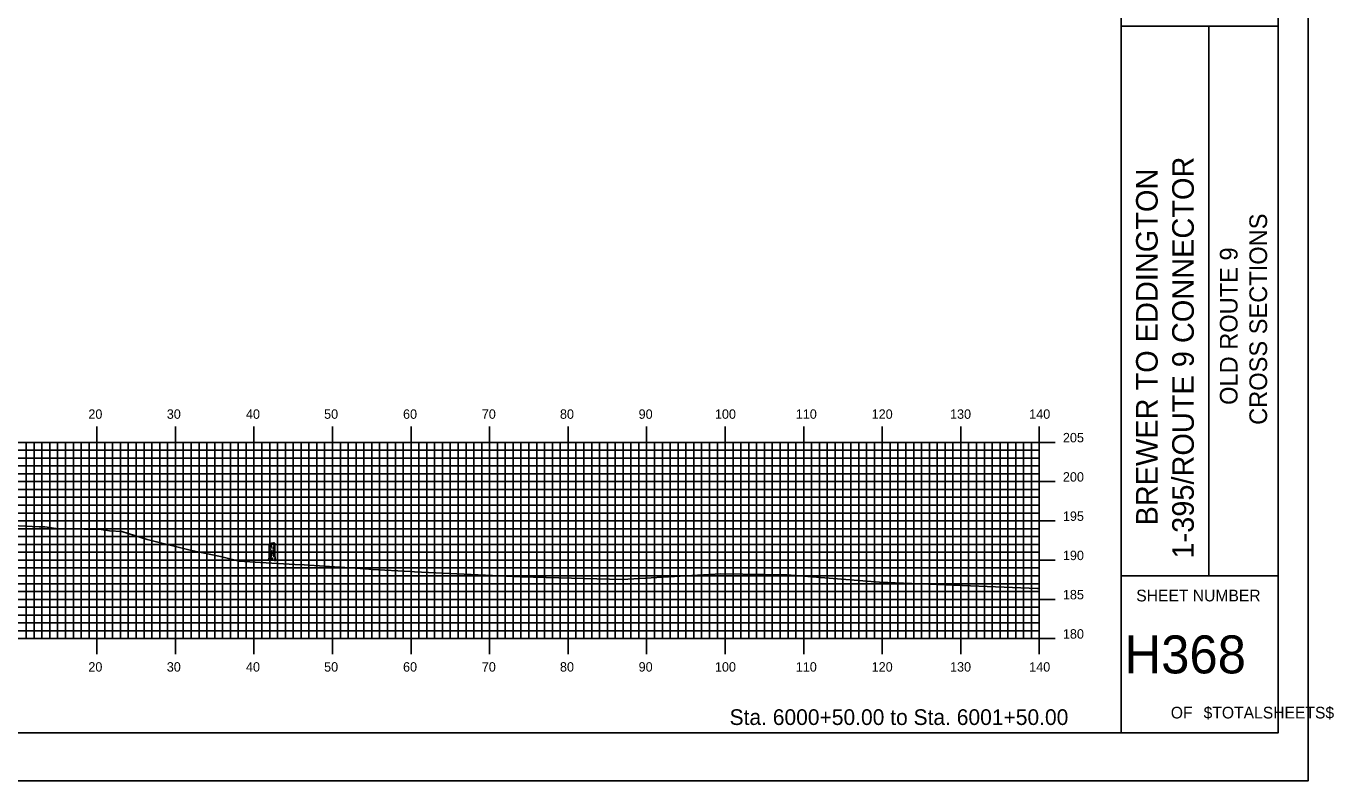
# Model space of a CAD drawing. Extents: x 851300 to 851643, y 366898 to 367118.
# Drawn here: x 851476.5 to 851643, y 366898.4 to 366994.5 of the extents above; entities that cross this region are included whole.
import ezdxf

# ---------------------------------------------------------------- set-up
doc = ezdxf.new("R2010")
doc.units = 0
for name, color, linetype in [('BORDER', 7, 'Continuous'), ('H_V ANNOTATION', 7, 'Continuous'), ('MAJOR', 7, 'Continuous'), ('MINOR', 7, 'Continuous'), ('PLOT BOUNDARY', 7, 'Continuous'), ('S_Roadway_Centerline', 7, 'Continuous'), ('S_Trees_Conifer_NonPay', 7, 'Continuous')]:
    doc.layers.add(name, color=color, linetype=linetype)

msp = doc.modelspace()

# ---------------------------------------------------------------- linework, layer by layer
at = {"layer": 'BORDER'}
for p, q in [((851615.9, 366904.47), (851615.9, 367114.47)), ((851615.9, 366994.48), (851635.9, 366994.48)), ((851627.09, 366924.48), (851627.09, 366994.48)), ((851615.9, 366924.48), (851635.9, 366924.48))]:
    msp.add_line(p, q, dxfattribs=at)
msp.add_lwpolyline([(851315.9, 366904.47), (851635.9, 366904.47), (851635.9, 367114.47), (851315.9, 367114.47)], close=True, dxfattribs=at)
at = {"layer": 'MAJOR'}
for p, q in [((851485.5, 366943.48), (851485.5, 366941.47)), ((851495.5, 366943.48), (851495.5, 366941.47)), ((851505.5, 366943.48), (851505.5, 366941.47)), ((851515.5, 366943.48), (851515.5, 366941.47)), ((851525.5, 366943.48), (851525.5, 366941.47)), ((851535.5, 366943.48), (851535.5, 366941.47)), ((851545.5, 366943.48), (851545.5, 366941.47)), ((851555.5, 366943.48), (851555.5, 366941.47)), ((851565.5, 366943.48), (851565.5, 366941.47)), ((851575.5, 366943.48), (851575.5, 366941.47)), ((851585.5, 366943.48), (851585.5, 366941.47)), ((851595.5, 366943.48), (851595.5, 366941.47)), ((851605.5, 366943.48), (851605.5, 366941.47)), ((851325.5, 366941.47), (851605.5, 366941.47)), ((851325.5, 366941.47), (851605.5, 366941.47)), ((851485.5, 366916.47), (851485.5, 366941.47)), ((851495.5, 366916.47), (851495.5, 366941.47)), ((851505.5, 366916.47), (851505.5, 366941.47)), ((851515.5, 366916.47), (851515.5, 366941.47)), ((851525.5, 366916.47), (851525.5, 366941.47)), ((851535.5, 366916.47), (851535.5, 366941.47)), ((851545.5, 366916.47), (851545.5, 366941.47)), ((851555.5, 366916.47), (851555.5, 366941.47)), ((851565.5, 366916.47), (851565.5, 366941.47)), ((851575.5, 366916.47), (851575.5, 366941.47)), ((851585.5, 366916.47), (851585.5, 366941.47)), ((851595.5, 366916.47), (851595.5, 366941.47)), ((851607.51, 366941.47), (851603.5, 366941.47)), ((851605.5, 366916.47), (851605.5, 366941.47)), ((851605.5, 366916.47), (851605.5, 366941.47)), ((851325.5, 366936.47), (851605.5, 366936.47)), ((851607.51, 366936.47), (851603.5, 366936.47)), ((851325.5, 366931.47), (851605.5, 366931.47)), ((851607.51, 366931.47), (851603.5, 366931.47)), ((851325.5, 366926.47), (851605.5, 366926.47)), ((851607.51, 366926.47), (851603.5, 366926.47)), ((851325.5, 366921.47), (851605.5, 366921.47)), ((851607.51, 366921.47), (851603.5, 366921.47)), ((851325.5, 366916.47), (851605.5, 366916.47)), ((851325.5, 366916.47), (851605.5, 366916.47)), ((851485.5, 366914.47), (851485.5, 366916.47)), ((851495.5, 366914.47), (851495.5, 366916.47)), ((851505.5, 366914.47), (851505.5, 366916.47)), ((851515.5, 366914.47), (851515.5, 366916.47)), ((851525.5, 366914.47), (851525.5, 366916.47)), ((851535.5, 366914.47), (851535.5, 366916.47)), ((851545.5, 366914.47), (851545.5, 366916.47)), ((851555.5, 366914.47), (851555.5, 366916.47)), ((851565.5, 366914.47), (851565.5, 366916.47)), ((851575.5, 366914.47), (851575.5, 366916.47)), ((851585.5, 366914.47), (851585.5, 366916.47)), ((851595.5, 366914.47), (851595.5, 366916.47)), ((851607.51, 366916.47), (851603.5, 366916.47)), ((851605.5, 366914.47), (851605.5, 366916.47))]:
    msp.add_line(p, q, dxfattribs=at)
at = {"layer": 'MINOR'}
for p, q in [((851476.5, 366916.47), (851476.5, 366941.47)), ((851477.5, 366916.47), (851477.5, 366941.47)), ((851478.5, 366916.47), (851478.5, 366941.47)), ((851479.5, 366916.47), (851479.5, 366941.47)), ((851480.5, 366916.47), (851480.5, 366941.47)), ((851481.5, 366916.47), (851481.5, 366941.47)), ((851482.5, 366916.47), (851482.5, 366941.47)), ((851483.5, 366916.47), (851483.5, 366941.47)), ((851484.5, 366916.47), (851484.5, 366941.47)), ((851486.5, 366916.47), (851486.5, 366941.47)), ((851487.5, 366916.47), (851487.5, 366941.47)), ((851488.5, 366916.47), (851488.5, 366941.47)), ((851489.5, 366916.47), (851489.5, 366941.47)), ((851490.5, 366916.47), (851490.5, 366941.47)), ((851491.5, 366916.47), (851491.5, 366941.47)), ((851492.5, 366916.47), (851492.5, 366941.47)), ((851493.5, 366916.47), (851493.5, 366941.47)), ((851494.5, 366916.47), (851494.5, 366941.47)), ((851496.5, 366916.47), (851496.5, 366941.47)), ((851497.5, 366916.47), (851497.5, 366941.47)), ((851498.5, 366916.47), (851498.5, 366941.47)), ((851499.5, 366916.47), (851499.5, 366941.47)), ((851500.5, 366916.47), (851500.5, 366941.47)), ((851501.5, 366916.47), (851501.5, 366941.47)), ((851502.5, 366916.47), (851502.5, 366941.47)), ((851503.5, 366916.47), (851503.5, 366941.47)), ((851504.5, 366916.47), (851504.5, 366941.47)), ((851506.5, 366916.47), (851506.5, 366941.47)), ((851507.5, 366916.47), (851507.5, 366941.47)), ((851508.5, 366916.47), (851508.5, 366941.47)), ((851509.5, 366916.47), (851509.5, 366941.47)), ((851510.5, 366916.47), (851510.5, 366941.47)), ((851511.5, 366916.47), (851511.5, 366941.47)), ((851512.5, 366916.47), (851512.5, 366941.47)), ((851513.5, 366916.47), (851513.5, 366941.47)), ((851514.5, 366916.47), (851514.5, 366941.47)), ((851516.5, 366916.47), (851516.5, 366941.47)), ((851517.5, 366916.47), (851517.5, 366941.47)), ((851518.5, 366916.47), (851518.5, 366941.47)), ((851519.5, 366916.47), (851519.5, 366941.47)), ((851520.5, 366916.47), (851520.5, 366941.47)), ((851521.5, 366916.47), (851521.5, 366941.47)), ((851522.5, 366916.47), (851522.5, 366941.47)), ((851523.5, 366916.47), (851523.5, 366941.47)), ((851524.5, 366916.47), (851524.5, 366941.47)), ((851526.5, 366916.47), (851526.5, 366941.47)), ((851527.5, 366916.47), (851527.5, 366941.47)), ((851528.5, 366916.47), (851528.5, 366941.47)), ((851529.5, 366916.47), (851529.5, 366941.47)), ((851530.5, 366916.47), (851530.5, 366941.47)), ((851531.5, 366916.47), (851531.5, 366941.47)), ((851532.5, 366916.47), (851532.5, 366941.47)), ((851533.5, 366916.47), (851533.5, 366941.47)), ((851534.5, 366916.47), (851534.5, 366941.47)), ((851536.5, 366916.47), (851536.5, 366941.47)), ((851537.5, 366916.47), (851537.5, 366941.47)), ((851538.5, 366916.47), (851538.5, 366941.47)), ((851539.5, 366916.47), (851539.5, 366941.47)), ((851540.5, 366916.47), (851540.5, 366941.47)), ((851541.5, 366916.47), (851541.5, 366941.47)), ((851542.5, 366916.47), (851542.5, 366941.47)), ((851543.5, 366916.47), (851543.5, 366941.47)), ((851544.5, 366916.47), (851544.5, 366941.47)), ((851546.5, 366916.47), (851546.5, 366941.47)), ((851547.5, 366916.47), (851547.5, 366941.47)), ((851548.5, 366916.47), (851548.5, 366941.47)), ((851549.5, 366916.47), (851549.5, 366941.47)), ((851550.5, 366916.47), (851550.5, 366941.47)), ((851551.5, 366916.47), (851551.5, 366941.47)), ((851552.5, 366916.47), (851552.5, 366941.47)), ((851553.5, 366916.47), (851553.5, 366941.47)), ((851554.5, 366916.47), (851554.5, 366941.47)), ((851556.5, 366916.47), (851556.5, 366941.47)), ((851557.5, 366916.47), (851557.5, 366941.47)), ((851558.5, 366916.47), (851558.5, 366941.47)), ((851559.5, 366916.47), (851559.5, 366941.47)), ((851560.5, 366916.47), (851560.5, 366941.47)), ((851561.5, 366916.47), (851561.5, 366941.47)), ((851562.5, 366916.47), (851562.5, 366941.47)), ((851563.5, 366916.47), (851563.5, 366941.47)), ((851564.5, 366916.47), (851564.5, 366941.47)), ((851566.5, 366916.47), (851566.5, 366941.47)), ((851567.5, 366916.47), (851567.5, 366941.47)), ((851568.5, 366916.47), (851568.5, 366941.47)), ((851569.5, 366916.47), (851569.5, 366941.47)), ((851570.5, 366916.47), (851570.5, 366941.47)), ((851571.5, 366916.47), (851571.5, 366941.47)), ((851572.5, 366916.47), (851572.5, 366941.47)), ((851573.5, 366916.47), (851573.5, 366941.47)), ((851574.5, 366916.47), (851574.5, 366941.47)), ((851576.5, 366916.47), (851576.5, 366941.47)), ((851577.5, 366916.47), (851577.5, 366941.47)), ((851578.5, 366916.47), (851578.5, 366941.47)), ((851579.5, 366916.47), (851579.5, 366941.47)), ((851580.5, 366916.47), (851580.5, 366941.47)), ((851581.5, 366916.47), (851581.5, 366941.47)), ((851582.5, 366916.47), (851582.5, 366941.47)), ((851583.5, 366916.47), (851583.5, 366941.47)), ((851584.5, 366916.47), (851584.5, 366941.47)), ((851586.5, 366916.47), (851586.5, 366941.47)), ((851587.5, 366916.47), (851587.5, 366941.47)), ((851588.5, 366916.47), (851588.5, 366941.47)), ((851589.5, 366916.47), (851589.5, 366941.47)), ((851590.5, 366916.47), (851590.5, 366941.47)), ((851591.5, 366916.47), (851591.5, 366941.47)), ((851592.5, 366916.47), (851592.5, 366941.47)), ((851593.5, 366916.47), (851593.5, 366941.47)), ((851594.5, 366916.47), (851594.5, 366941.47)), ((851596.5, 366916.47), (851596.5, 366941.47)), ((851597.5, 366916.47), (851597.5, 366941.47)), ((851598.5, 366916.47), (851598.5, 366941.47)), ((851599.5, 366916.47), (851599.5, 366941.47)), ((851600.5, 366916.47), (851600.5, 366941.47)), ((851601.5, 366916.47), (851601.5, 366941.47)), ((851602.5, 366916.47), (851602.5, 366941.47)), ((851603.5, 366916.47), (851603.5, 366941.47)), ((851604.5, 366916.47), (851604.5, 366941.47)), ((851325.5, 366940.47), (851605.5, 366940.47)), ((851325.5, 366939.47), (851605.5, 366939.47)), ((851605.5, 366940.47), (851603.5, 366940.47)), ((851605.5, 366939.47), (851603.5, 366939.47)), ((851325.5, 366938.47), (851605.5, 366938.47)), ((851325.5, 366937.47), (851605.5, 366937.47)), ((851605.5, 366938.47), (851603.5, 366938.47)), ((851605.5, 366937.47), (851603.5, 366937.47)), ((851325.5, 366935.47), (851605.5, 366935.47)), ((851325.5, 366934.47), (851605.5, 366934.47)), ((851605.5, 366935.47), (851603.5, 366935.47)), ((851605.5, 366934.47), (851603.5, 366934.47)), ((851325.5, 366933.47), (851605.5, 366933.47)), ((851325.5, 366932.47), (851605.5, 366932.47)), ((851605.5, 366933.47), (851603.5, 366933.47)), ((851605.5, 366932.47), (851603.5, 366932.47)), ((851325.5, 366930.47), (851605.5, 366930.47)), ((851325.5, 366929.47), (851605.5, 366929.47)), ((851605.5, 366930.47), (851603.5, 366930.47)), ((851605.5, 366929.47), (851603.5, 366929.47)), ((851325.5, 366928.47), (851605.5, 366928.47)), ((851325.5, 366927.47), (851605.5, 366927.47)), ((851605.5, 366928.47), (851603.5, 366928.47)), ((851605.5, 366927.47), (851603.5, 366927.47)), ((851325.5, 366925.47), (851605.5, 366925.47)), ((851325.5, 366924.47), (851605.5, 366924.47)), ((851605.5, 366925.47), (851603.5, 366925.47)), ((851605.5, 366924.47), (851603.5, 366924.47)), ((851325.5, 366923.47), (851605.5, 366923.47)), ((851325.5, 366922.47), (851605.5, 366922.47)), ((851605.5, 366923.47), (851603.5, 366923.47)), ((851605.5, 366922.47), (851603.5, 366922.47)), ((851325.5, 366920.47), (851605.5, 366920.47)), ((851325.5, 366919.47), (851605.5, 366919.47)), ((851605.5, 366920.47), (851603.5, 366920.47)), ((851605.5, 366919.47), (851603.5, 366919.47)), ((851325.5, 366918.47), (851605.5, 366918.47)), ((851325.5, 366917.47), (851605.5, 366917.47)), ((851605.5, 366918.47), (851603.5, 366918.47)), ((851605.5, 366917.47), (851603.5, 366917.47))]:
    msp.add_line(p, q, dxfattribs=at)
at = {"layer": 'PLOT BOUNDARY'}
msp.add_lwpolyline([(851299.72, 366898.35), (851639.72, 366898.35), (851639.72, 367118.35), (851299.72, 367118.35)], close=True, dxfattribs=at)
at = {"layer": 'S_Roadway_Centerline'}
msp.add_lwpolyline([(851471.09, 366931.06), (851478.15, 366930.7), (851478.87, 366930.71), (851480.28, 366930.51), (851481.66, 366930.45), (851486.03, 366930.37), (851487.09, 366930.21), (851488.67, 366930.11), (851490.28, 366929.59), (851491.91, 366929.11), (851497.56, 366927.7), (851501.22, 366926.93), (851503.62, 366926.34), (851506.31, 366926.16), (851510.72, 366925.93), (851511.88, 366925.88), (851519.66, 366925.36), (851520.54, 366925.27), (851525.45, 366925.01), (851525.94, 366924.99), (851526.82, 366924.94), (851539.49, 366924.36), (851552.38, 366924), (851564.93, 366924.72), (851573.33, 366924.6), (851585.69, 366923.63), (851586.01, 366923.63), (851586.21, 366923.62), (851587.14, 366923.59), (851605.26, 366922.86), (851605.5, 366922.86)], dxfattribs=at)
at = {"layer": 'S_Trees_Conifer_NonPay'}
for p, q in [((851507.5, 366927.36), (851507.5, 366927.26)), ((851507.52, 366928.46), (851507.52, 366928.25)), ((851507.52, 366928.18), (851507.52, 366927.85)), ((851507.52, 366927.74), (851507.52, 366927.66)), ((851507.52, 366927.54), (851507.52, 366927.43)), ((851507.68, 366928.33), (851507.68, 366928.06)), ((851507.68, 366927.71), (851507.68, 366927.39)), ((851507.72, 366927.34), (851507.72, 366927.27)), ((851507.94, 366928.51), (851507.94, 366928.44)), ((851507.94, 366928.19), (851507.94, 366927.86)), ((851507.94, 366927.76), (851507.94, 366927.61)), ((851507.94, 366927.38), (851507.94, 366927.14)), ((851508.07, 366928.23), (851508.07, 366928.09)), ((851508.07, 366927.99), (851508.07, 366927.76)), ((851508.07, 366927.67), (851508.07, 366927.29)), ((851507.52, 366927.14), (851507.52, 366926.88)), ((851507.68, 366927.22), (851507.68, 366927.06)), ((851507.68, 366927), (851507.68, 366926.87)), ((851507.94, 366927.08), (851507.94, 366927)), ((851508.05, 366927.1), (851508.07, 366926.85)), ((851508.13, 366926.87), (851508.19, 366926.88))]:
    msp.add_line(p, q, dxfattribs=at)
for points in [[(851507.44, 366928.49), (851507.44, 366926.78), (851507.37, 366926.52), (851507.25, 366926.48), (851507.47, 366926.47), (851507.63, 366926.41), (851507.84, 366926.47), (851508.1, 366926.42), (851508.3, 366926.43), (851508.15, 366926.53), (851508.08, 366926.68)], [(851508.07, 366928.55), (851508.07, 366928.46), (851508.07, 366928.29)], [(851508.18, 366926.51), (851508.3, 366926.52), (851508.21, 366926.64), (851508.17, 366927.18), (851508.15, 366927.7), (851508.15, 366928.62)], [(851507.47, 366926.47), (851507.56, 366926.58), (851507.57, 366926.69)], [(851507.6, 366926.83), (851507.59, 366926.79), (851507.64, 366926.78), (851507.64, 366926.84)], [(851507.84, 366926.47), (851507.79, 366926.64), (851507.79, 366926.81)], [(851507.79, 366926.69), (851507.86, 366926.69), (851507.88, 366926.74)]]:
    msp.add_lwpolyline(points, dxfattribs=at)
for centre, radius, start, end in [((851507.5, 366928.46), 0.0729, 130.3798, 141.6195), ((851507.47, 366928.49), 0.0263, 141.6195, 160.3798), ((851507.46, 366928.49), 0.0186, 160.3798, 174.3267), ((851507.45, 366928.49), 0.0141, 174.3267, 190.3798), ((851507.45, 366928.49), 0.0141, 190.3798, 206.433), ((851507.46, 366928.5), 0.0186, 206.433, 220.3798), ((851507.46, 366928.5), 0.0263, 220.3798, 239.1402), ((851507.45, 366928.38), 0.0143, 180, 196.0515), ((851507.45, 366927.91), 0.0143, 180, 196.0515), ((851507.46, 366927.91), 0.0189, 196.0515, 210), ((851507.47, 366927.92), 0.0267, 210, 228.7494), ((851507.45, 366927.7), 0.0143, 180, 196.0515), ((851507.46, 366927.7), 0.0189, 196.0515, 210), ((851507.47, 366927.71), 0.0267, 210, 228.7494), ((851507.45, 366927.26), 0.0143, 180, 196.0515), ((851507.61, 366928.33), 0.245, 108.3946, 130.3798), ((851507.49, 366928.54), 0.0729, 239.1402, 250.3798), ((851507.5, 366927.95), 0.0738, 228.7494, 240), ((851507.5, 366927.74), 0.0738, 228.7494, 240), ((851507.55, 366928.7), 0.245, 250.3798, 272.3651), ((851507.58, 366928.1), 0.245, 240, 246.7914), ((851507.58, 366927.89), 0.245, 240, 254.9514), ((851507.58, 366928.31), 0.245, 244.3148, 257.5375), ((851507.58, 366928.57), 0.245, 254.8461, 261.8968), ((851507.58, 366928.1), 0.245, 254.8461, 257.5454), ((851507.58, 366927.67), 0.245, 254.9814, 261.8968), ((851508.11, 366926.83), 1.83, 100.3798, 108.3946), ((851507.8, 366930.07), 1.77, 261.8968, 262.605), ((851507.8, 366929.18), 1.77, 261.8968, 262.45), ((851507.48, 366930.28), 1.83, 272.3651, 280.3798), ((851507.8, 366930.07), 1.77, 264.3267, 266.0499), ((851507.8, 366929.61), 1.77, 265.2285, 266.1325), ((851507.8, 366929.82), 1.77, 265.8991, 267.5962), ((851507.8, 366929.4), 1.77, 266.0429, 268.5525), ((851508.11, 366926.83), 1.83, 92.3651, 100.3798), ((851507.48, 366930.28), 1.83, 280.3798, 288.3946), ((851507.8, 366929.82), 1.77, 272.7221, 274.4847), ((851507.8, 366929.4), 1.77, 274.5361, 277.0026), ((851507.8, 366930.07), 1.77, 276.2449, 278.1032), ((851507.8, 366929.18), 1.77, 276.7966, 278.1032), ((851508.05, 366928.41), 0.245, 70.3798, 92.3651), ((851508.01, 366928.57), 0.245, 278.1032, 284.1859), ((851508.01, 366927.67), 0.245, 278.1032, 284.3207), ((851507.98, 366928.78), 0.245, 288.3946, 310.3798), ((851508.01, 366928.1), 0.245, 284.1859, 300), ((851508.01, 366928.57), 0.245, 291.7653, 300), ((851508.01, 366927.89), 0.245, 292.1924, 300), ((851508.1, 366928.57), 0.0729, 59.1402, 70.3798), ((851508.1, 366928.42), 0.0738, 300, 311.2506), ((851508.1, 366927.95), 0.0738, 300, 311.2506), ((851508.1, 366927.74), 0.0738, 300, 311.2506), ((851508.13, 366928.61), 0.0263, 40.3798, 59.1402), ((851508.09, 366928.65), 0.0729, 310.3798, 321.6195), ((851508.13, 366928.62), 0.0186, 26.433, 40.3798), ((851508.14, 366928.62), 0.0141, 10.3798, 26.433), ((851508.13, 366928.62), 0.0186, 340.3798, 354.3267), ((851508.14, 366928.62), 0.0141, 354.3267, 10.3798), ((851508.13, 366928.62), 0.0263, 321.6195, 340.3798), ((851508.13, 366928.38), 0.0267, 311.2506, 330), ((851508.13, 366928.38), 0.0189, 330, 343.9485), ((851508.13, 366928.13), 0.0267, 311.2506, 330), ((851508.14, 366928.13), 0.0189, 330, 343.9485), ((851508.13, 366927.91), 0.0189, 330, 343.9485), ((851508.13, 366927.92), 0.0267, 311.2506, 330), ((851508.13, 366927.7), 0.0189, 330, 343.9485), ((851508.13, 366927.71), 0.0267, 311.2506, 330), ((851507.45, 366927.06), 0.0143, 180, 196.0515), ((851507.46, 366927.06), 0.0189, 196.0515, 210), ((851507.46, 366927.06), 0.0267, 210, 228.7494), ((851507.5, 366927.1), 0.0738, 228.7494, 240), ((851507.58, 366927.25), 0.245, 240, 249.1675), ((851507.8, 366928.96), 1.77, 262.2622, 265.0496), ((851507.8, 366928.75), 1.77, 266.0862, 268.2187), ((851507.8, 366928.96), 1.77, 272.6293, 274.5612), ((851507.8, 366928.75), 1.77, 274.2776, 276.3006), ((851507.8, 366928.96), 1.77, 277.63, 278.1032), ((851508.01, 366927.45), 0.245, 278.1032, 294.6056), ((851508.01, 366927.25), 0.245, 284.0684, 300), ((851508.1, 366927.1), 0.0738, 300, 302.05)]:
    msp.add_arc(centre, radius, start, end, dxfattribs=at)

# ---------------------------------------------------------------- texts
at = {"layer": 'BORDER'}
for s, height, p in [('1-395/ROUTE 9 CONNECTOR', 2.7557, (851625.17, 366926.67)), ('BREWER TO EDDINGTON', 2.7557, (851620.57, 366930.88)), ('CROSS SECTIONS', 2.25, (851634.5, 366943.7)), ('OLD ROUTE 9', 2.25, (851630.74, 366946.24))]:
    msp.add_text(s, height=height, rotation=90, dxfattribs=at).set_placement(p)
for s, height, p in [('SHEET NUMBER', 1.4905, (851617.84, 366921.21)), ('H368', 4.839, (851616.34, 366912.04)), ('OF', 1.491, (851622.24, 366906.3)), ('$TOTALSHEETS$', 1.4905, (851626.42, 366906.3))]:
    msp.add_text(s, height=height, dxfattribs=at).set_placement(p)
at = {"layer": 'H_V ANNOTATION'}
for s, height, p in [('20', 1.2, (851484.41, 366944.47)), ('30', 1.2, (851494.4, 366944.47)), ('40', 1.2, (851504.48, 366944.47)), ('50', 1.2, (851514.43, 366944.47)), ('60', 1.2, (851524.48, 366944.47)), ('70', 1.2, (851534.51, 366944.47)), ('80', 1.2, (851544.46, 366944.47)), ('90', 1.2, (851554.48, 366944.47)), ('100', 1.2, (851564.19, 366944.47)), ('110', 1.2, (851574.49, 366944.47)), ('120', 1.2, (851584.15, 366944.47)), ('130', 1.2, (851594.13, 366944.47)), ('140', 1.2, (851604.21, 366944.47)), ('205', 1.2, (851608.5, 366941.47)), ('200', 1.2, (851608.5, 366936.47)), ('195', 1.2, (851608.5, 366931.47)), ('190', 1.2, (851608.5, 366926.47)), ('185', 1.2, (851608.5, 366921.47)), ('180', 1.2, (851608.5, 366916.47)), ('20', 1.2, (851484.41, 366912.27)), ('30', 1.2, (851494.4, 366912.27)), ('40', 1.2, (851504.48, 366912.27)), ('50', 1.2, (851514.43, 366912.27)), ('60', 1.2, (851524.48, 366912.27)), ('70', 1.2, (851534.51, 366912.27)), ('80', 1.2, (851544.46, 366912.27)), ('90', 1.2, (851554.48, 366912.27)), ('100', 1.2, (851564.19, 366912.27)), ('110', 1.2, (851574.49, 366912.27)), ('120', 1.2, (851584.15, 366912.27)), ('130', 1.2, (851594.13, 366912.27)), ('140', 1.2, (851604.21, 366912.27)), ('Sta. 6000+50.00 to Sta. 6001+50.00', 2.0004, (851566.06, 366905.47))]:
    msp.add_text(s, height=height, dxfattribs=at).set_placement(p)

doc.saveas('drawing.dxf')
